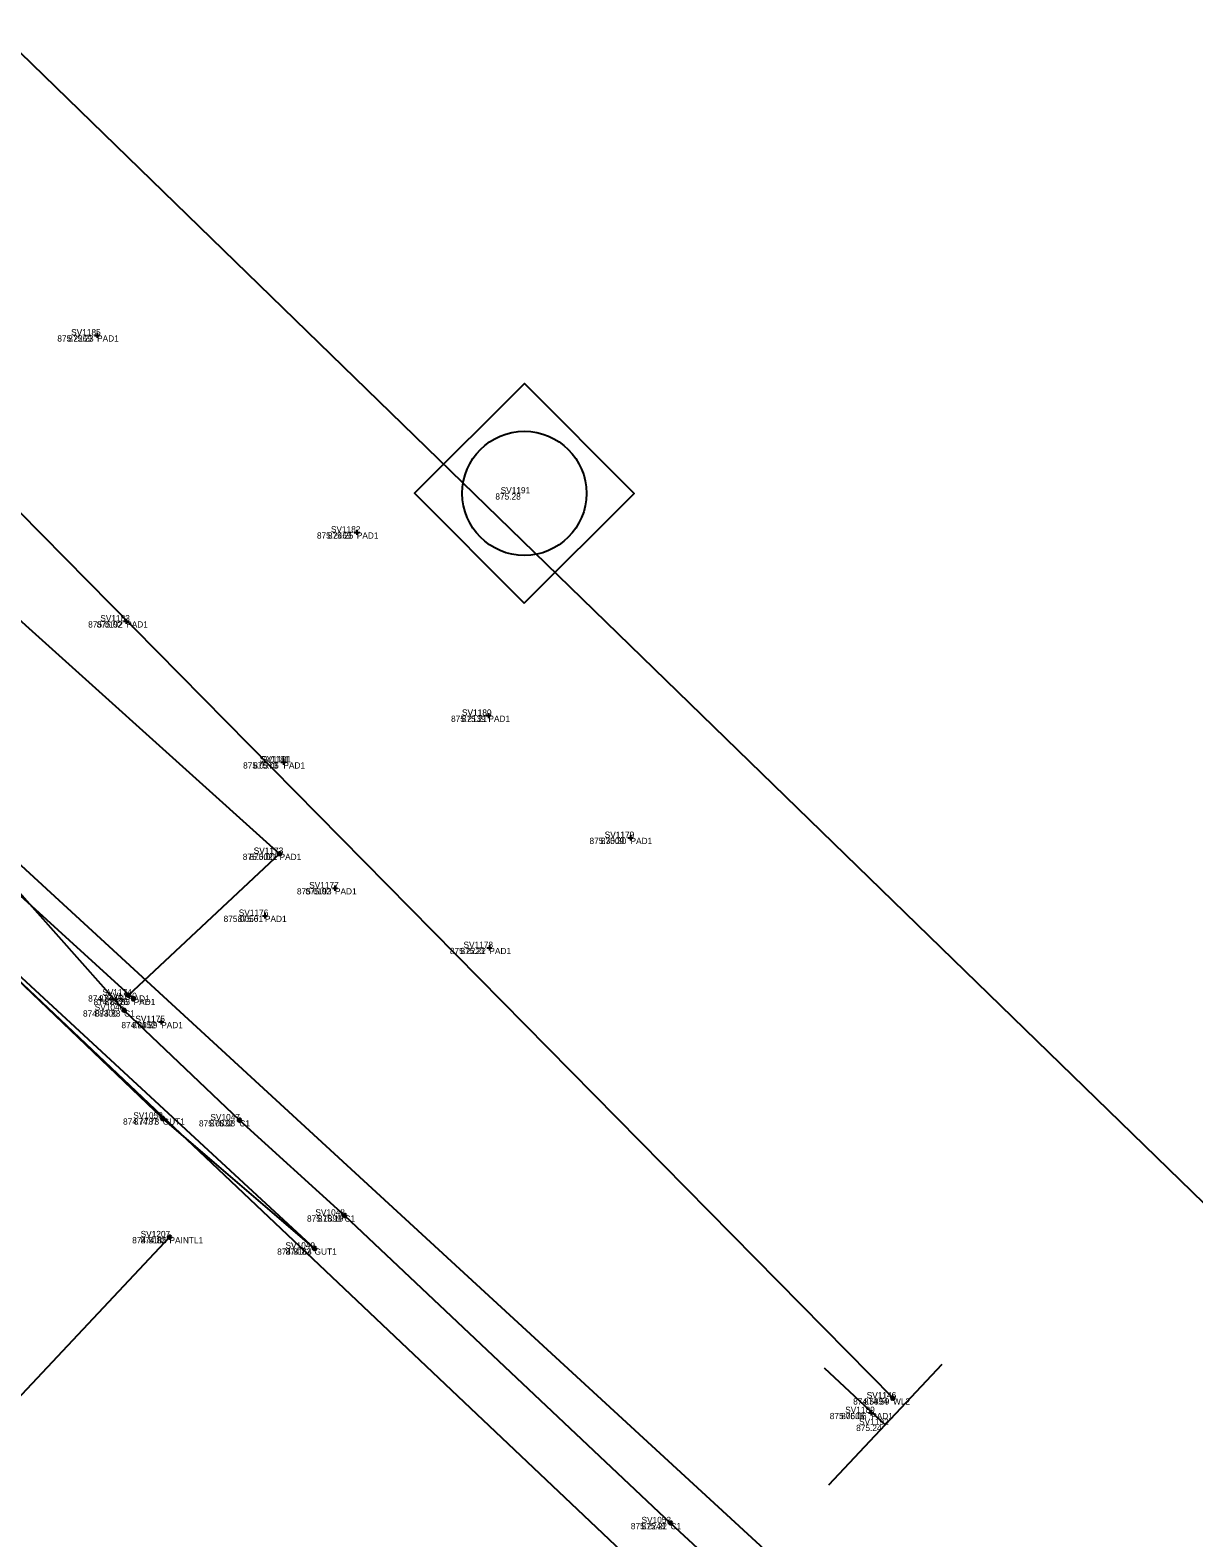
# Model space of a CAD drawing. Extents: x 1475924 to 1484301, y 375879 to 383357.
# Drawn here: x 1480215.72 to 1480226.96, y 379406.42 to 379420.99 of the extents above; entities that cross this region are included whole.
import ezdxf

# ---------------------------------------------------------------- set-up
doc = ezdxf.new("R2010")
doc.units = 0
for name, color, linetype in [('PM_X_Crosswalk', 7, 'Continuous'), ('PV_X_Curb', 7, 'Continuous'), ('PV_X_Walk', 7, 'Continuous'), ('RD_X_Concrete_Pad', 7, 'Continuous'), ('SG_X_Poles', 7, 'Continuous'), ('SN_X_Public', 7, 'Continuous'), ('SV_X_Shot_Marker', 7, 'Continuous'), ('SV_X_Text_Comment', 7, 'Continuous'), ('SV_X_Text_Elevation', 7, 'Continuous'), ('SV_X_Text_Name', 7, 'Continuous'), ('UT_X_Water', 7, 'Continuous')]:
    doc.layers.add(name, color=color, linetype=linetype)

# ---------------------------------------------------------------- blocks, each defined once
blk = doc.blocks.new('GTM')
at = {"layer": 'SV_X_Shot_Marker'}
for p, q in [((-0.075, 0), (0.075, 0)), ((0, 0.075), (0, -0.075)), ((0, 0), (0, 0))]:
    blk.add_line(p, q, dxfattribs=at)
blk = doc.blocks.new('SPOLE')
at = {"layer": 'SG_X_Poles'}
blk.add_lwpolyline([(-0.075, -0.075), (0.075, -0.075), (0.075, 0.075), (-0.075, 0.075)], close=True, dxfattribs=at)
blk.add_circle((0, 0), 0.06, dxfattribs=at)
blk = doc.blocks.new('SGN1P')
at = {"layer": 'SN_X_Public'}
for p, q in [((0, 0.08), (0, -0.08)), ((0, 0), (-0.08, 0))]:
    blk.add_line(p, q, dxfattribs=at)

msp = doc.modelspace()

# ---------------------------------------------------------------- linework, layer by layer
at = {"layer": 'PM_X_Crosswalk'}
msp.add_line((1480217.07, 379409.327), (1480190.411, 379380.931), dxfattribs=at)
at = {"layer": 'PV_X_Curb'}
for points in [[(1480121.053, 379501.135), (1480146.64, 379476.909), (1480171.177, 379454.102), (1480173.021, 379452.229), (1480182.175, 379443.675), (1480183.379, 379442.683), (1480186.184, 379440.013), (1480186.975, 379439.363), (1480207.407, 379420.301), (1480210.41, 379417.305), (1480211.712, 379416.16), (1480212.774, 379415.29), (1480213.67, 379414.243), (1480215.361, 379412.945), (1480216.632, 379411.517), (1480217.745, 379410.456), (1480218.76, 379409.536), (1480221.908, 379406.565), (1480233.156, 379396.15)], [(1480138.714, 379483.703), (1480170.84, 379453.681), (1480172.574, 379452.083), (1480181.867, 379443.345), (1480182.839, 379442.217), (1480185.607, 379439.661), (1480186.493, 379438.955), (1480206.919, 379419.855), (1480210.187, 379416.932), (1480211.433, 379415.804), (1480213.11, 379414.171), (1480218.471, 379409.217), (1480217.005, 379410.473), (1480215.222, 379412.175), (1480221.495, 379406.235), (1480232.955, 379395.538)]]:
    msp.add_lwpolyline(points, dxfattribs=at)
at = {"layer": 'PV_X_Walk'}
msp.add_lwpolyline([(1480235.613, 379401.335), (1480215.341, 379421.047), (1480197.466, 379437.463), (1480177.803, 379455.97), (1480154.79, 379476.967), (1480132.747, 379497.48), (1480113.376, 379516.728), (1480110.754, 379519.04), (1480109.877, 379518.336), (1480091.944, 379535.267), (1480093.027, 379536.619), (1480090.219, 379539.243), (1480090.463, 379539.725), (1480084.681, 379544.882), (1480083.843, 379544.144), (1480066.818, 379560.524), (1480045.662, 379580.046)], dxfattribs=at)
at = {"layer": 'RD_X_Concrete_Pad'}
msp.add_lwpolyline([(1480216.724, 379411.628), (1480213.809, 379414.28), (1480215.189, 379415.676), (1480218.133, 379413.03), (1480216.67, 379411.662)], dxfattribs=at)
at = {"layer": 'SV_X_Shot_Marker'}
for p, q in [((1480216.346, 379418.037), (1480216.396, 379418.037)), ((1480216.371, 379418.062), (1480216.371, 379418.012)), ((1480216.371, 379418.037), (1480216.371, 379418.037)), ((1480218.854, 379416.134), (1480218.904, 379416.134)), ((1480218.879, 379416.159), (1480218.879, 379416.109)), ((1480218.879, 379416.134), (1480218.879, 379416.134)), ((1480216.627, 379415.275), (1480216.677, 379415.275)), ((1480216.652, 379415.3), (1480216.652, 379415.25)), ((1480216.652, 379415.275), (1480216.652, 379415.275)), ((1480220.15, 379414.389), (1480220.15, 379414.339)), ((1480220.125, 379414.364), (1480220.175, 379414.364)), ((1480220.15, 379414.364), (1480220.15, 379414.364)), ((1480218.145, 379413.913), (1480218.195, 379413.913)), ((1480218.17, 379413.938), (1480218.17, 379413.888)), ((1480218.17, 379413.913), (1480218.17, 379413.913)), ((1480221.497, 379413.184), (1480221.547, 379413.184)), ((1480221.522, 379413.209), (1480221.522, 379413.159)), ((1480221.522, 379413.184), (1480221.522, 379413.184)), ((1480218.114, 379413.046), (1480218.151, 379413.013)), ((1480218.149, 379413.048), (1480218.116, 379413.011)), ((1480218.133, 379413.03), (1480218.133, 379413.03)), ((1480218.643, 379412.697), (1480218.693, 379412.697)), ((1480218.668, 379412.722), (1480218.668, 379412.672)), ((1480218.668, 379412.697), (1480218.668, 379412.697)), ((1480217.967, 379412.431), (1480218.017, 379412.431)), ((1480217.992, 379412.456), (1480217.992, 379412.406)), ((1480217.992, 379412.431), (1480217.992, 379412.431)), ((1480220.134, 379412.121), (1480220.184, 379412.121)), ((1480220.159, 379412.146), (1480220.159, 379412.096)), ((1480220.159, 379412.121), (1480220.159, 379412.121)), ((1480216.688, 379411.679), (1480216.652, 379411.645)), ((1480216.687, 379411.644), (1480216.653, 379411.68)), ((1480216.67, 379411.662), (1480216.67, 379411.662)), ((1480216.742, 379411.612), (1480216.705, 379411.645)), ((1480216.707, 379411.61), (1480216.741, 379411.647)), ((1480216.724, 379411.628), (1480216.724, 379411.628)), ((1480216.65, 379411.533), (1480216.613, 379411.5)), ((1480216.615, 379411.535), (1480216.648, 379411.498)), ((1480216.632, 379411.517), (1480216.632, 379411.517)), ((1480216.965, 379411.405), (1480217.015, 379411.405)), ((1480216.99, 379411.43), (1480216.99, 379411.38)), ((1480216.99, 379411.405), (1480216.99, 379411.405)), ((1480217.024, 379410.457), (1480216.986, 379410.49)), ((1480216.989, 379410.454), (1480217.021, 379410.492)), ((1480217.005, 379410.473), (1480217.005, 379410.473)), ((1480217.727, 379410.474), (1480217.763, 379410.439)), ((1480217.762, 379410.474), (1480217.728, 379410.438)), ((1480217.745, 379410.456), (1480217.745, 379410.456)), ((1480218.741, 379409.553), (1480218.778, 379409.519)), ((1480218.776, 379409.555), (1480218.743, 379409.518)), ((1480218.76, 379409.536), (1480218.76, 379409.536)), ((1480217.089, 379409.309), (1480217.052, 379409.344)), ((1480217.088, 379409.345), (1480217.053, 379409.308)), ((1480217.07, 379409.327), (1480217.07, 379409.327)), ((1480218.453, 379409.234), (1480218.49, 379409.2)), ((1480218.488, 379409.235), (1480218.454, 379409.198)), ((1480218.471, 379409.217), (1480218.471, 379409.217)), ((1480224.039, 379407.753), (1480224.075, 379407.788)), ((1480224.075, 379407.752), (1480224.04, 379407.788)), ((1480224.057, 379407.77), (1480224.057, 379407.77)), ((1480223.821, 379407.629), (1480223.871, 379407.629)), ((1480223.846, 379407.654), (1480223.846, 379407.604)), ((1480223.846, 379407.629), (1480223.846, 379407.629)), ((1480221.89, 379406.582), (1480221.926, 379406.548)), ((1480221.925, 379406.583), (1480221.891, 379406.547)), ((1480221.908, 379406.565), (1480221.908, 379406.565))]:
    msp.add_line(p, q, dxfattribs=at)
at = {"layer": 'UT_X_Water'}
msp.add_line((1480224.057, 379407.77), (1480199.329, 379432.864), dxfattribs=at)
msp.add_lwpolyline([(1480049.152, 379568.017), (1480068.611, 379550.193), (1480086.403, 379533.424), (1480090.024, 379530.079), (1480102.295, 379519.134), (1480111.734, 379511.473), (1480120.332, 379509.136), (1480127.535, 379501.668), (1480127.911, 379496.395), (1480140.166, 379484.084), (1480149.088, 379474.708), (1480164.726, 379459.482), (1480172.622, 379452.503), (1480197.813, 379429.111), (1480212.628, 379415.684), (1480231.592, 379398.237)], dxfattribs=at)

# ---------------------------------------------------------------- block references
at = {"layer": 'SG_X_Poles', "xscale": 10, "yscale": 10, "rotation": 44.873503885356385}
msp.add_blockref('SPOLE', (1480220.497, 379416.511), dxfattribs=at)
at = {"layer": 'SN_X_Public', "xscale": 10, "yscale": 10.000000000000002, "rotation": -43.12149650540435}
msp.add_blockref('SGN1P', (1480223.98, 379407.514), dxfattribs=at)
at = {"layer": 'SV_X_Shot_Marker', "xscale": 0.3333333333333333, "yscale": 0.3333333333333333}
for p in [(1480216.371, 379418.037), (1480218.879, 379416.134), (1480216.652, 379415.275), (1480220.15, 379414.364), (1480218.17, 379413.913), (1480221.522, 379413.184), (1480218.133, 379413.03), (1480218.668, 379412.697), (1480217.992, 379412.431), (1480220.159, 379412.121), (1480216.67, 379411.662), (1480216.724, 379411.628), (1480216.632, 379411.517), (1480216.99, 379411.405), (1480217.005, 379410.473), (1480217.745, 379410.456), (1480218.76, 379409.536), (1480217.07, 379409.327), (1480218.471, 379409.217), (1480224.057, 379407.77), (1480223.846, 379407.629), (1480221.908, 379406.565)]:
    msp.add_blockref('GTM', p, dxfattribs=at)

# ---------------------------------------------------------------- texts
at = {"layer": 'SV_X_Text_Comment'}
for s, p in [('PAD1', (1480216.371, 379417.977)), ('PAD1', (1480218.879, 379416.074)), ('PAD1', (1480216.652, 379415.215)), ('PAD1', (1480220.15, 379414.304)), ('PAD1', (1480218.17, 379413.853)), ('PAD1', (1480221.522, 379413.124)), ('PAD1', (1480218.133, 379412.97)), ('PAD1', (1480218.668, 379412.637)), ('PAD1', (1480217.992, 379412.371)), ('PAD1', (1480220.159, 379412.061)), ('PAD1', (1480216.67, 379411.602)), ('PAD1', (1480216.724, 379411.568)), ('C1', (1480216.632, 379411.457)), ('PAD1', (1480216.99, 379411.345)), ('GUT1', (1480217.005, 379410.413)), ('C1', (1480217.745, 379410.396)), ('C1', (1480218.76, 379409.476)), ('PAINTL1', (1480217.07, 379409.267)), ('GUT1', (1480218.471, 379409.157)), ('WL2', (1480224.057, 379407.71)), ('PAD1', (1480223.846, 379407.569)), ('C1', (1480221.908, 379406.505))]:
    msp.add_text(s, height=0.06, dxfattribs=at).set_placement(p)
at = {"layer": 'SV_X_Text_Elevation'}
for s, p in [('875.2269', (1480215.987, 379417.977)), ('875.23', (1480216.092, 379417.977)), ('875.23', (1480216.092, 379417.977)), ('875.28', (1480220.217, 379416.451)), ('875.28', (1480220.217, 379416.451)), ('875.2469', (1480218.494, 379416.074)), ('875.25', (1480218.6, 379416.074)), ('875.25', (1480218.6, 379416.074)), ('875.0192', (1480216.285, 379415.215)), ('875.02', (1480216.367, 379415.215)), ('875.02', (1480216.367, 379415.215)), ('875.2139', (1480219.789, 379414.304)), ('875.21', (1480219.893, 379414.304)), ('875.21', (1480219.893, 379414.304)), ('875.0573', (1480217.781, 379413.853)), ('875.06', (1480217.88, 379413.853)), ('875.06', (1480217.88, 379413.853)), ('875.3009', (1480221.126, 379413.124)), ('875.30', (1480221.236, 379413.124)), ('875.30', (1480221.236, 379413.124)), ('875.0021', (1480217.778, 379412.97)), ('875.00', (1480217.842, 379412.97)), ('875.00', (1480217.842, 379412.97)), ('875.0193', (1480218.301, 379412.637)), ('875.02', (1480218.383, 379412.637)), ('875.02', (1480218.383, 379412.637)), ('875.0056', (1480217.593, 379412.371)), ('875.01', (1480217.729, 379412.371)), ('875.01', (1480217.729, 379412.371)), ('875.2223', (1480219.778, 379412.061)), ('875.22', (1480219.88, 379412.061)), ('875.22', (1480219.88, 379412.061)), ('874.8445', (1480216.285, 379411.602)), ('874.8526', (1480216.337, 379411.568)), ('874.84', (1480216.39, 379411.602)), ('874.84', (1480216.39, 379411.602)), ('874.85', (1480216.443, 379411.568)), ('874.85', (1480216.443, 379411.568)), ('874.8300', (1480216.235, 379411.457)), ('874.83', (1480216.351, 379411.457)), ('874.83', (1480216.351, 379411.457)), ('874.8852', (1480216.606, 379411.345)), ('874.89', (1480216.709, 379411.345)), ('874.89', (1480216.709, 379411.345)), ('874.7787', (1480216.622, 379410.413)), ('874.78', (1480216.725, 379410.413)), ('874.78', (1480216.725, 379410.413)), ('875.0832', (1480217.355, 379410.396)), ('875.08', (1480217.459, 379410.396)), ('875.08', (1480217.459, 379410.396)), ('875.1899', (1480218.398, 379409.476)), ('875.19', (1480218.503, 379409.476)), ('875.19', (1480218.503, 379409.476)), ('874.8185', (1480216.71, 379409.267)), ('874.82', (1480216.79, 379409.267)), ('874.82', (1480216.79, 379409.267)), ('874.8164', (1480218.11, 379409.157)), ('874.82', (1480218.191, 379409.157)), ('874.82', (1480218.191, 379409.157)), ('874.5894', (1480223.672, 379407.71)), ('874.59', (1480223.776, 379407.71)), ('874.59', (1480223.776, 379407.71)), ('875.0606', (1480223.446, 379407.569)), ('875.06', (1480223.556, 379407.569)), ('875.06', (1480223.556, 379407.569)), ('875.24', (1480223.701, 379407.454)), ('875.24', (1480223.701, 379407.454)), ('875.2248', (1480221.525, 379406.505)), ('875.22', (1480221.629, 379406.505)), ('875.22', (1480221.629, 379406.505))]:
    msp.add_text(s, height=0.06, dxfattribs=at).set_placement(p)
at = {"layer": 'SV_X_Text_Name'}
for s, p in [('SV1185', (1480216.12, 379418.037)), ('SV1185', (1480216.121, 379418.037)), ('SV1185', (1480216.121, 379418.037)), ('SV1191', (1480220.268, 379416.511)), ('SV1191', (1480220.268, 379416.511)), ('SV1182', (1480218.629, 379416.134)), ('SV1182', (1480218.629, 379416.134)), ('SV1182', (1480218.629, 379416.134)), ('SV1183', (1480216.402, 379415.275)), ('SV1183', (1480216.402, 379415.275)), ('SV1183', (1480216.402, 379415.275)), ('SV1180', (1480219.895, 379414.364)), ('SV1180', (1480219.894, 379414.364)), ('SV1180', (1480219.894, 379414.364)), ('SV1181', (1480217.942, 379413.913)), ('SV1181', (1480217.942, 379413.913)), ('SV1181', (1480217.959, 379413.913)), ('SV1179', (1480221.273, 379413.184)), ('SV1179', (1480221.272, 379413.184)), ('SV1179', (1480221.272, 379413.184)), ('SV1173', (1480217.883, 379413.03)), ('SV1173', (1480217.884, 379413.03)), ('SV1173', (1480217.884, 379413.03)), ('SV1177', (1480218.419, 379412.697)), ('SV1177', (1480218.419, 379412.697)), ('SV1177', (1480218.419, 379412.697)), ('SV1176', (1480217.739, 379412.431)), ('SV1176', (1480217.739, 379412.431)), ('SV1176', (1480217.739, 379412.431)), ('SV1178', (1480219.909, 379412.121)), ('SV1178', (1480219.909, 379412.121)), ('SV1178', (1480219.909, 379412.121)), ('SV1174', (1480216.421, 379411.662)), ('SV1174', (1480216.421, 379411.662)), ('SV1174', (1480216.421, 379411.662)), ('SV1170', (1480216.469, 379411.628)), ('SV1170', (1480216.469, 379411.628)), ('SV1170', (1480216.469, 379411.628)), ('SV1046', (1480216.348, 379411.517)), ('SV1046', (1480216.348, 379411.517)), ('SV1046', (1480216.348, 379411.517)), ('SV1175', (1480216.74, 379411.405)), ('SV1175', (1480216.741, 379411.405)), ('SV1175', (1480216.741, 379411.405)), ('SV1050', (1480216.72, 379410.473)), ('SV1050', (1480216.72, 379410.473)), ('SV1050', (1480216.72, 379410.473)), ('SV1047', (1480217.465, 379410.456)), ('SV1047', (1480217.465, 379410.456)), ('SV1047', (1480217.465, 379410.456)), ('SV1048', (1480218.479, 379409.536)), ('SV1048', (1480218.479, 379409.536)), ('SV1048', (1480218.479, 379409.536)), ('SV1207', (1480216.792, 379409.327)), ('SV1207', (1480216.791, 379409.327)), ('SV1207', (1480216.791, 379409.327)), ('SV1049', (1480218.191, 379409.217)), ('SV1049', (1480218.19, 379409.217)), ('SV1049', (1480218.19, 379409.217)), ('SV1146', (1480223.803, 379407.77)), ('SV1146', (1480223.802, 379407.77)), ('SV1146', (1480223.802, 379407.77)), ('SV1189', (1480223.595, 379407.629)), ('SV1189', (1480223.595, 379407.629)), ('SV1189', (1480223.595, 379407.629)), ('SV1192', (1480223.729, 379407.514)), ('SV1192', (1480223.729, 379407.514)), ('SV1053', (1480221.628, 379406.565)), ('SV1053', (1480221.628, 379406.565)), ('SV1053', (1480221.628, 379406.565))]:
    msp.add_text(s, height=0.06, dxfattribs=at).set_placement(p)

doc.saveas('drawing.dxf')
